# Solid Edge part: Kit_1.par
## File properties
Author: bmolnar
Last saved by: bmolnar
Revision: 78
Sűrűség: 0,000 kg/m^3
Pontosság: 0,990
Username: bmolnar
Dokumentum tartalom típus: 0
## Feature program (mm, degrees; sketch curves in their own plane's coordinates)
base feature "unnamed BaseFeature 1"
sketch for "unnamed Hole 1" plane through (23.25, -23.25, 5) normal (0, 0, -1) x-axis (0, 1, 0)
  hole centre (0, 0) bore radius 3.3235
hole "unnamed Hole 1" through
sketch for "unnamed Hole 2" plane through (23.25, -23.25, 5) normal (0, 0, -1) x-axis (0, 1, 0)
  hole centre (46.5, 0) bore radius 3.3235
hole "unnamed Hole 2" through
sketch for "unnamed Hole 3" plane through (23.25, -23.25, 5) normal (0, 0, -1) x-axis (0, 1, 0)
  hole centre (46.5, -46.5) bore radius 3.3235
hole "unnamed Hole 3" through
sketch for "unnamed Hole 4" plane through (23.25, -23.25, 5) normal (0, 0, -1) x-axis (0, 1, 0)
  hole centre (0, -46.5) bore radius 3.3235
hole "unnamed Hole 4" through
pattern "unnamed Pattern 1" of "unnamed Hole 1", "unnamed Hole 2", "unnamed Hole 3", "unnamed Hole 4"
sketch for "Furat_5" plane through (-32.75, 0, -18.25) normal (1, 0, 0) x-axis (0, -1, 0)
  hole centre (0, -26.25) bore radius 4.283
hole "Furat_5" nominal diameter 9.728 finite  ThreadDepth = 10 mm
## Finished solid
Body 1: solid body, 302 faces, 729 edges, 446 vertices, 4 internal voids.
  Faces by surface: plane 139, cylinder 78, swept 53, torus 20, cone 11, spline 1
  Edges by curve: line 413, circle 160, spline 118, ellipse 28, curve on surface 10
Bounding box of the edges (mm; curved faces can reach further): 65.500 x 65.500 x 14.500, from (-32.75, -32.75, 0) to (32.75, 32.75, 14.5).
Cylindrical faces by radius (mm): R0.2 x40, R0.201 x2, R0.2012 x2, R2.5402 x12, R2.6 x4, R3.3235 x4, R3.75 x4, R3.85 x4, R4.283 x1, R5.25 x4, R6 x1
Conical faces (half-angle, radius in mm at the cone's reference point): 0.5 deg R6.5 x2, 0.5 deg R8 x4, 45 deg R3.6735 x4, 45 deg R6.15 x1
Toroidal faces (ring radius, tube radius in mm): R2.9402 r0.4 x12, R3.55 r0.2 x8
Planar faces by outward normal: +x 11, +y 12, +z 1, -x 13, -y 12, -z 22, oblique 68
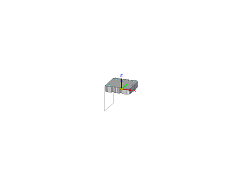
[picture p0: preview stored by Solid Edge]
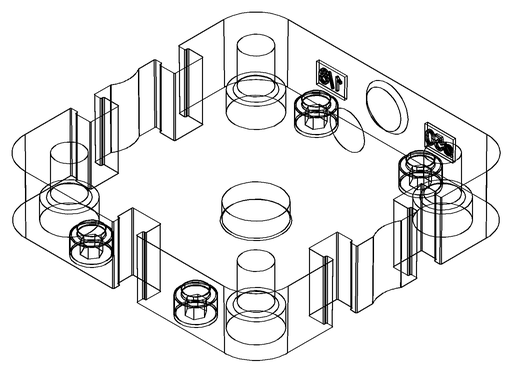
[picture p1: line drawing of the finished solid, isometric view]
